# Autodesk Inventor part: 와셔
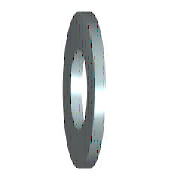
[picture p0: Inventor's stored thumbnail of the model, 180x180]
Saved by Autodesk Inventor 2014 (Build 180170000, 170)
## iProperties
Created: 2012-02
Part Number: 와셔
Material: 강철, 연강
Description: 평면 와셔
Document SubType Name: Modeling
Standard: KS B 1326
Designer: mduedu
Standards Organization: KS
Language: ko-KR
Size Designation: 8x15.5
Categories: <MemberInstance><Categories><Category DisplayName="조임쇠" InternalName="e4da775c-781d-43d5-af7c-5136215cf5a6" Mnemonic="FSTN"><Category DisplayName="와셔" InternalN
Density: 1 g/cm^3
Appearance: 파란색 - 벽 페인트 - 광택
IsCustomPart: 1
Author: mduedu
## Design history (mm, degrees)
sketch "스케치"
  geometry: C1 r 7.75 at (0, 0); C2 r 4.2 at (0, 0); 1 further point
  constraints: 2 centre point, 2 coincident
  dimensions: "d0" = 8.4 diameter of C2 (= SD1); "d1" = 15.5 diameter of C1 (= SD2)
extrude "본체" new body sketch "스케치" distance "d2" = 1.6 (= SD); taper "d3" = 0 deg
workaxis "Work Axis1"
workplane "Work Plane1"
body "Solid1"
other parameters: "SD1" = 8.4 [user parameter; used in 1 equation term], "SD2" = 15.5 [user parameter; used in 1 equation term], "SD" = 1.6 [user parameter; used in 1 equation term], "d4" = 0, "d5" = 0, "d6" = 0, "d7" = 0, "NND" = 8 [user parameter]
